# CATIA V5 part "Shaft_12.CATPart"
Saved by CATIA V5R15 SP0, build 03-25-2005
Part number: Shaft_12
Bounding box of the stored display mesh (mm): x -23.8 to 23.8, y -23.8 to 23.8, z 0 to 948
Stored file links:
  E:\#01 CATIA Lecture Materials\#06 DMU\#11 DMU Page01 KIN EX11\Shaft_12.CATPart
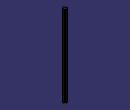
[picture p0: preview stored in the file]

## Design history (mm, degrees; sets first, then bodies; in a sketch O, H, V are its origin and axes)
Body1 (main body)
  Sketch1 on xy-plane, origin (0, 0, 0), H (1, 0, 0), V (0, 1, 0)
    arc A1 centre (0, 0) radius 23.8 from (21.9289, -9.25) to (21.9289, 9.25) ccw
    line L1 (-21.9289, 9.25) -> (-9.25, 9.25)
    line L2 (21.9289, -9.25) -> (9.25, -9.25)
    line L3 (9.25, 21.9289) -> (9.25, 9.25)
    line L4 (-9.25, -21.9289) -> (-9.25, -9.25)
    point P4 (-9.25, -21.9289)
    arc A2 centre (0, 0) radius 23.8 from (-9.25, -21.9289) to (9.25, -21.9289) ccw
    point P6 (-21.9289, 9.25)
    arc A3 centre (0, 0) radius 23.8 from (-21.9289, 9.25) to (-21.9289, -9.25) ccw
    point P8 (9.25, 21.9289)
    arc A4 centre (0, 0) radius 23.8 from (9.25, 21.9289) to (-9.25, 21.9289) ccw
    point P9 (-9.25, 9.25)
    line L5 (9.25, 9.25) -> (21.9289, 9.25)
    line L6 (9.25, -9.25) -> (9.25, -21.9289)
    line L7 (-9.25, 9.25) -> (-9.25, 21.9289)
    point P12 (-9.25, -9.25)
    line L8 (-9.25, -9.25) -> (-21.9289, -9.25)
    radius A1 = 23.8
    distance L1 L2 = 18.5
    distance H L1 = 9.25
    distance L3 L4 = 18.5
    distance V L3 = 9.25
    horizontal: L1 H, L2 H, L5 H, L8 H
    vertical: L3 V, L4 V, L6 V, L7 V
    coincidence: A1 P4, A1 A2, A1 P6, A1 A3, A1 P8, A1 A4, L4 P9, L1 L5, L3 L6, L2 P12, L4 L7, L2 L8
  Pad1: profile Sketch1, direction (0, 0, 1), length 948
  Fillet1: radius 2, on edge [face of Pad1 | face of Pad1] (x4)
  Fillet2: radius 2, on face of Pad1 (x2)
  Fillet3: radius 2, on edge [face of Pad1 from Sketch1.L8 | face of Pad1 from Sketch1.A3]; edge [face of Pad1 from Sketch1.A2 | face of Pad1 from Sketch1.L4]; edge [face of Pad1 from Sketch1.L6 | face of Pad1 from Sketch1.A2]; edge [face of Pad1 from Sketch1.A1 | face of Pad1 from Sketch1.L2]; edge [face of Pad1 from Sketch1.L5 | face of Pad1 from Sketch1.A1]; edge [face of Pad1 from Sketch1.A4 | face of Pad1 from Sketch1.L3]; edge [face of Pad1 from Sketch1.A3 | face of Pad1 from Sketch1.L1]; edge [face of Pad1 from Sketch1.L7 | face of Pad1 from Sketch1.A4]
